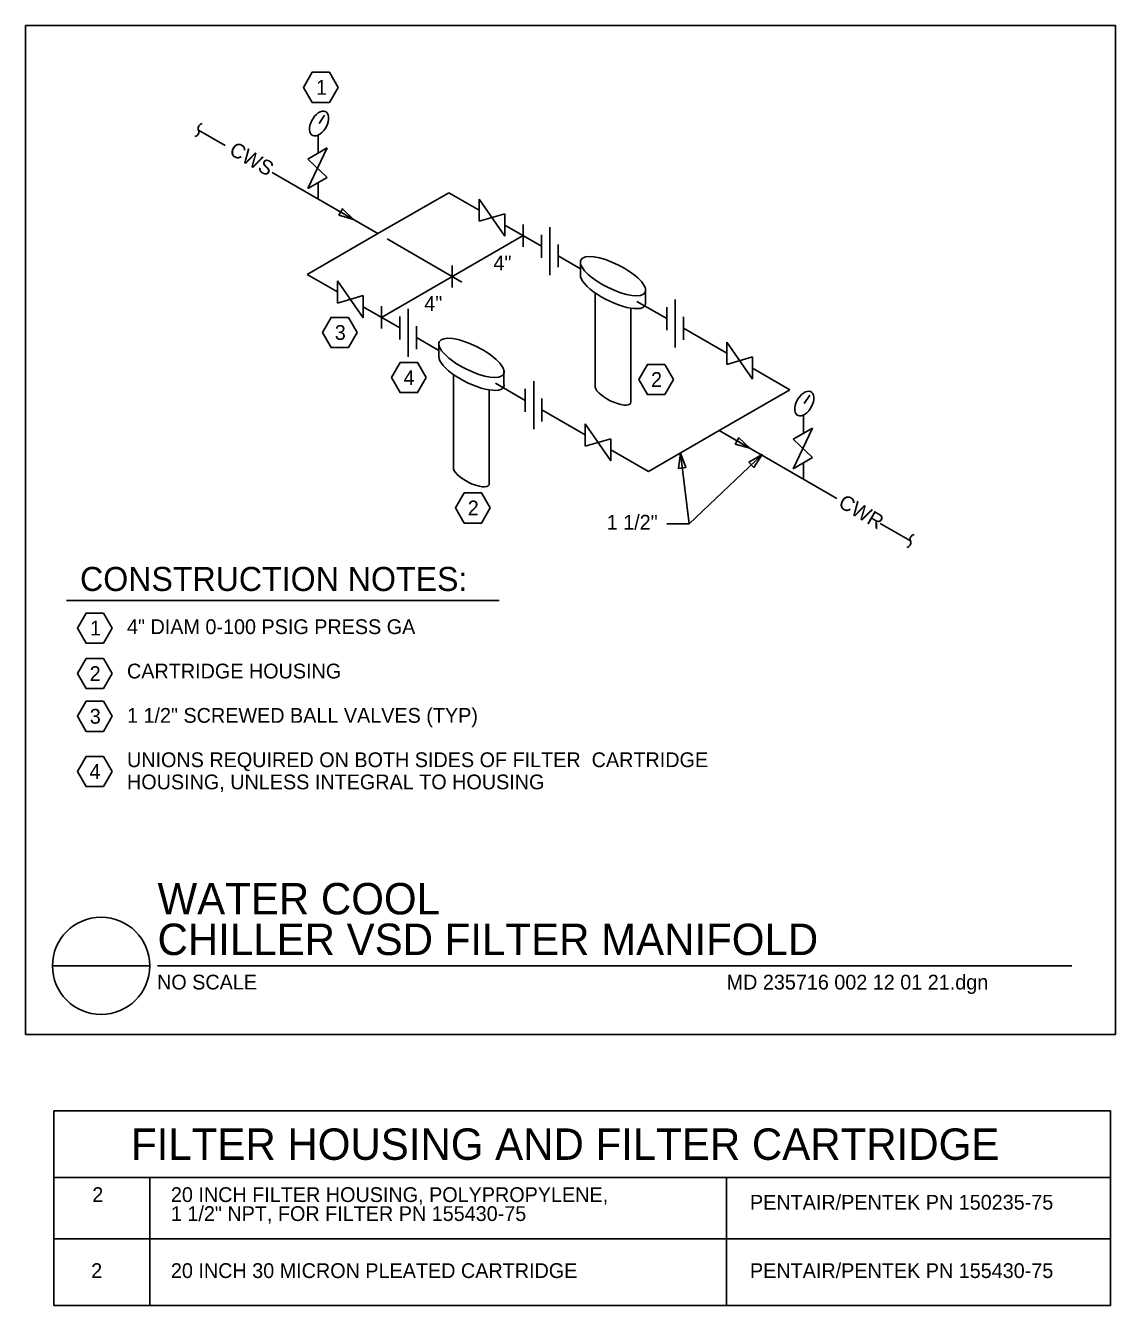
# Model space of a CAD drawing. Extents: x 10150.1 to 10199.2, y 10347.9 to 10405.7.
import ezdxf

# ---------------------------------------------------------------- set-up
doc = ezdxf.new("R2010")
doc.units = 0
for name, color, linetype in [('G-ANNO-CELL', 7, 'Continuous'), ('G-ANNO-SYMB', 7, 'Continuous'), ('G-DETL-GRID', 7, 'Continuous'), ('G-DETL-LINE', 7, 'Continuous'), ('G-DETL-TEXT', 7, 'Continuous'), ('G-SCHD-LINE', 7, 'Continuous'), ('G-SCHD-TEXT', 7, 'Continuous'), ('G-SCHD-TTXT', 7, 'Continuous')]:
    doc.layers.add(name, color=color, linetype=linetype)

msp = doc.modelspace()

# ---------------------------------------------------------------- linework, layer by layer
at = {"layer": 'G-ANNO-CELL'}
for p, q in [((10151.928, 10379.737), (10171.437, 10379.737)), ((10151.293, 10363.264), (10155.678, 10363.264)), ((10156.024, 10363.264), (10197.259, 10363.264))]:
    msp.add_line(p, q, dxfattribs=at)
msp.add_circle((10153.485, 10363.264), 2.193, dxfattribs=at)
at = {"layer": 'G-ANNO-SYMB'}
for points in [[(10164.174, 10402.882), (10163.782, 10402.202), (10162.998, 10402.202), (10162.606, 10402.882), (10162.998, 10403.561), (10163.782, 10403.561)], [(10165.03, 10391.828), (10164.638, 10391.149), (10163.854, 10391.149), (10163.462, 10391.828), (10163.854, 10392.507), (10164.638, 10392.507)], [(10168.146, 10389.794), (10167.754, 10389.115), (10166.97, 10389.115), (10166.578, 10389.794), (10166.97, 10390.473), (10167.754, 10390.473)], [(10179.296, 10389.706), (10178.904, 10389.027), (10178.12, 10389.027), (10177.727, 10389.706), (10178.12, 10390.385), (10178.904, 10390.385)], [(10171.033, 10383.914), (10170.641, 10383.234), (10169.857, 10383.234), (10169.465, 10383.914), (10169.857, 10384.593), (10170.641, 10384.593)], [(10153.983, 10378.496), (10153.591, 10377.817), (10152.807, 10377.817), (10152.415, 10378.496), (10152.807, 10379.175), (10153.591, 10379.175)], [(10153.983, 10376.444), (10153.591, 10375.765), (10152.807, 10375.765), (10152.415, 10376.444), (10152.807, 10377.123), (10153.591, 10377.123)], [(10153.983, 10374.518), (10153.591, 10373.839), (10152.807, 10373.839), (10152.415, 10374.518), (10152.807, 10375.197), (10153.591, 10375.197)], [(10153.983, 10372.026), (10153.591, 10371.347), (10152.807, 10371.347), (10152.415, 10372.026), (10152.807, 10372.705), (10153.591, 10372.705)]]:
    msp.add_lwpolyline(points, close=True, dxfattribs=at)
at = {"layer": 'G-DETL-GRID'}
for p, q in [((10150.081, 10405.668), (10199.223, 10405.669)), ((10150.081, 10405.668), (10150.081, 10360.168)), ((10199.223, 10405.669), (10199.223, 10360.169)), ((10150.081, 10360.168), (10199.223, 10360.169))]:
    msp.add_line(p, q, dxfattribs=at)
at = {"layer": 'G-DETL-LINE'}
for p, q in [((10163.314, 10401.251), (10163.562, 10401.636)), ((10159.077, 10400.267), (10157.88, 10400.958)), ((10162.883, 10400.96), (10162.883, 10400.961)), ((10163.277, 10400.731), (10163.277, 10399.917)), ((10163.68, 10400.149), (10162.814, 10399.649)), ((10162.814, 10398.316), (10163.68, 10400.149)), ((10162.814, 10399.649), (10163.68, 10398.816)), ((10165.966, 10396.289), (10161.203, 10399.039)), ((10162.814, 10398.316), (10163.68, 10398.816)), ((10163.277, 10398.583), (10163.277, 10397.842)), ((10169.158, 10398.132), (10165.966, 10396.289)), ((10170.528, 10397.341), (10169.158, 10398.132)), ((10170.528, 10397.841), (10170.528, 10396.841)), ((10170.528, 10397.841), (10171.683, 10396.174)), ((10171.683, 10397.174), (10170.528, 10396.841)), ((10171.683, 10396.174), (10171.683, 10397.174)), ((10173.342, 10395.716), (10171.683, 10396.674)), ((10172.512, 10396.695), (10172.512, 10395.695)), ((10173.722, 10396.577), (10173.722, 10394.417)), ((10165.966, 10396.289), (10162.774, 10394.447)), ((10172.512, 10396.195), (10166.129, 10392.51)), ((10169.754, 10394.102), (10166.382, 10396.049)), ((10173.342, 10396.234), (10173.342, 10395.198)), ((10174.089, 10395.803), (10174.089, 10394.767)), ((10175.097, 10394.703), (10174.089, 10395.285)), ((10169.321, 10394.852), (10169.321, 10393.852)), ((10175.097, 10394.411), (10175.097, 10394.994)), ((10164.145, 10393.655), (10162.774, 10394.447)), ((10164.145, 10394.155), (10164.145, 10393.155)), ((10164.145, 10394.155), (10165.3, 10392.489)), ((10175.762, 10393.614), (10175.762, 10389.359)), ((10178.035, 10393.202), (10178.035, 10393.785)), ((10165.3, 10393.489), (10164.145, 10393.155)), ((10165.3, 10392.489), (10165.3, 10393.489)), ((10166.958, 10392.031), (10165.3, 10392.989)), ((10166.129, 10393.01), (10166.129, 10392.01)), ((10178.995, 10392.452), (10177.649, 10393.229)), ((10178.995, 10392.97), (10178.995, 10391.934)), ((10179.375, 10393.313), (10179.375, 10391.153)), ((10166.958, 10392.549), (10166.958, 10391.513)), ((10167.339, 10392.891), (10167.339, 10390.731)), ((10177.374, 10392.922), (10177.374, 10388.675)), ((10179.743, 10392.539), (10179.743, 10391.503)), ((10167.706, 10392.117), (10167.706, 10391.081)), ((10181.701, 10390.89), (10179.743, 10392.021)), ((10168.714, 10391.018), (10167.706, 10391.599)), ((10168.714, 10390.726), (10168.714, 10391.309)), ((10181.701, 10391.39), (10181.701, 10390.39)), ((10181.701, 10391.39), (10182.855, 10389.724)), ((10182.855, 10390.724), (10181.701, 10390.39)), ((10182.855, 10389.724), (10182.855, 10390.724)), ((10171.652, 10389.517), (10171.652, 10390.1)), ((10184.549, 10389.246), (10182.855, 10390.224)), ((10169.379, 10389.929), (10169.379, 10385.673)), ((10172.612, 10388.767), (10171.266, 10389.544)), ((10172.992, 10389.627), (10172.992, 10387.467)), ((10170.991, 10389.237), (10170.991, 10384.99)), ((10172.612, 10389.285), (10172.612, 10388.249)), ((10184.549, 10389.246), (10181.357, 10387.403)), ((10185.192, 10388.62), (10185.44, 10389.005)), ((10173.359, 10388.853), (10173.359, 10387.817)), ((10175.317, 10387.205), (10173.359, 10388.335)), ((10184.76, 10388.329), (10184.76, 10388.33)), ((10185.155, 10388.1), (10185.155, 10387.286)), ((10175.317, 10387.705), (10175.317, 10386.705)), ((10175.317, 10387.705), (10176.472, 10386.038)), ((10181.357, 10387.403), (10178.165, 10385.561)), ((10186.659, 10384.342), (10181.357, 10387.403)), ((10185.558, 10387.518), (10184.692, 10387.018)), ((10184.692, 10385.685), (10185.558, 10387.518)), ((10176.472, 10387.038), (10175.317, 10386.705)), ((10176.472, 10386.038), (10176.472, 10387.038)), ((10184.692, 10387.018), (10185.558, 10386.185)), ((10178.165, 10385.561), (10176.472, 10386.538)), ((10180, 10383.198), (10179.612, 10386.382)), ((10180, 10383.198), (10183.295, 10386.321)), ((10184.692, 10385.685), (10185.558, 10386.185)), ((10185.155, 10385.952), (10185.155, 10385.211)), ((10179, 10383.198), (10180, 10383.198)), ((10189.982, 10382.424), (10188.616, 10383.213))]:
    msp.add_line(p, q, dxfattribs=at)
for points in [[(10164.198, 10397.118), (10164.859, 10396.929), (10164.365, 10397.406)], [(10182.078, 10386.795), (10182.739, 10386.606), (10182.245, 10387.083)], [(10179.527, 10385.7), (10179.612, 10386.382), (10179.858, 10385.741)], [(10182.696, 10385.984), (10183.295, 10386.321), (10182.925, 10385.742)]]:
    msp.add_lwpolyline(points, close=True, dxfattribs=at)
for centre, start, end in [((10158.071, 10401.04), 96.8699, 203.1301), ((10157.688, 10400.876), 276.8699, 23.1301), ((10190.173, 10382.506), 96.8699, 203.1301), ((10189.79, 10382.342), 276.8699, 23.1301)]:
    msp.add_arc(centre, 0.208, start, end, dxfattribs=at)
for centre, major_axis, ratio, start_param, end_param in [((10163.314, 10401.251), (0.306, 0.53), 0.57735, 2.439043, 8.721433), ((10176.568, 10393.785), (-1.45, 0.728), 0.345306, 0.163125, 3.389428), ((10170.185, 10390.1), (-1.45, 0.728), 0.345306, 0.163125, 3.389428), ((10176.568, 10389.034), (-0.795, 0.399), 0.345306, 0.234526, 3.351491), ((10185.192, 10388.62), (0.306, 0.53), 0.57735, 2.439043, 8.721433), ((10170.184, 10385.349), (-0.795, 0.399), 0.345306, 0.234526, 3.351491)]:
    msp.add_ellipse(centre, major_axis=major_axis, ratio=ratio, start_param=start_param, end_param=end_param, dxfattribs=at)
for centre in [(10176.568, 10394.368), (10170.185, 10390.683)]:
    msp.add_ellipse(centre, major_axis=(-1.45, 0.728), ratio=0.345306, dxfattribs=at)
at = {"layer": 'G-SCHD-LINE'}
for p, q in [((10151.355, 10356.722), (10198.997, 10356.722)), ((10151.355, 10356.722), (10151.355, 10347.949)), ((10198.997, 10356.722), (10198.997, 10347.949)), ((10151.355, 10353.722), (10198.997, 10353.722)), ((10155.688, 10353.722), (10155.688, 10347.949)), ((10181.688, 10353.722), (10181.688, 10347.949)), ((10151.355, 10350.949), (10198.997, 10350.949)), ((10151.355, 10347.949), (10198.997, 10347.949))]:
    msp.add_line(p, q, dxfattribs=at)

# ---------------------------------------------------------------- texts
at = {"layer": 'G-ANNO-CELL'}
for s, height, p in [('CONSTRUCTION NOTES:', 1.08333, (10152.536, 10380.17)), ('WATER COOL', 1.4167, (10156.03, 10365.584)), ('CHILLER VSD FILTER MANIFOLD', 1.41667, (10156.03, 10363.751)), ('NO SCALE', 0.6667, (10156.008, 10362.197))]:
    msp.add_text(s, height=height, dxfattribs=at).set_placement(p)
at = {"layer": 'G-ANNO-SYMB'}
for s, p in [('1', (10163.177, 10402.548)), ('3', (10164.022, 10391.495)), ('4', (10167.123, 10389.461)), ('2', (10178.282, 10389.373)), ('2', (10170.019, 10383.58)), ('1', (10152.986, 10378.163)), ('2', (10152.969, 10376.11)), ('3', (10152.975, 10374.185)), ('4', (10152.96, 10371.693))]:
    msp.add_text(s, height=0.667, dxfattribs=at).set_placement(p)
at = {"layer": 'G-DETL-TEXT'}
for s, p in [('CWS', (10159.21, 10399.891)), ('CWR', (10186.678, 10383.988))]:
    msp.add_text(s, height=0.6667, rotation=330, dxfattribs=at).set_placement(p)
for s, height, p in [('4"', 0.6667, (10171.176, 10394.63)), ('4"', 0.6667, (10168.059, 10392.804)), ('1 1/2"', 0.6667, (10176.285, 10382.936)), ('4" DIAM 0-100 PSIG PRESS GA', 0.66667, (10154.653, 10378.225)), ('CARTRIDGE HOUSING', 0.66667, (10154.653, 10376.225)), ('1 1/2" SCREWED BALL VALVES (TYP)', 0.66667, (10154.653, 10374.225)), ('UNIONS REQUIRED ON BOTH SIDES OF FILTER  CARTRIDGE', 0.66667, (10154.653, 10372.225)), ('HOUSING, UNLESS INTEGRAL TO HOUSING', 0.66667, (10154.653, 10371.225)), ('MD 235716 002 12 01 21.dgn', 0.66667, (10181.691, 10362.195))]:
    msp.add_text(s, height=height, dxfattribs=at).set_placement(p)
at = {"layer": 'G-SCHD-TEXT'}
for s, height, p in [('2', 0.667, (10153.087, 10352.612)), ('20 INCH FILTER HOUSING, POLYPROPYLENE,', 0.66667, (10156.633, 10352.612)), ('PENTAIR/PENTEK PN 150235-75', 0.66667, (10182.745, 10352.267)), ('1 1/2" NPT, FOR FILTER PN 155430-75', 0.66667, (10156.633, 10351.756)), ('2', 0.667, (10153.038, 10349.184)), ('20 INCH 30 MICRON PLEATED CARTRIDGE', 0.66667, (10156.633, 10349.184)), ('PENTAIR/PENTEK PN 155430-75', 0.66667, (10182.745, 10349.184))]:
    msp.add_text(s, height=height, dxfattribs=at).set_placement(p)
at = {"layer": 'G-SCHD-TTXT'}
msp.add_text('FILTER HOUSING AND FILTER CARTRIDGE', height=1.41667, dxfattribs=at).set_placement((10154.834, 10354.514))

doc.saveas('drawing.dxf')
